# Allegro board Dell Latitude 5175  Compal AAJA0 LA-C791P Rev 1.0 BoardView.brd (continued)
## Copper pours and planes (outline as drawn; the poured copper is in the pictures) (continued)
CPU_B+ on TOP (solid shape): 108.91,124.06 108.91,117.72 108.81,117.62 108.81,114.33 108.9,114.24 108.9,113.72 108.97,113.66 109.58,113.66 109.6,113.63 109.6,112.97 109.55,112.92 106.86,112.92 106.32,113.45 106.32,116.56 106.9,116.56 106.9,117.45 106.32,117.45 106.32,117.77 106.9,117.77 106.9,118.6 106.32,118.6 106.32,119.09 106.78,119.55 106.78,120.82 106.79,120.84 106.79,122.13 106.79,122.14 106.79,123.87 107.09,124.17 108.81,124.17
CPU_B+ on BOTTOM (solid shape): 112.5,121.27 112.5,117.66 112.39,117.55 112.29,117.55 112.17,117.66 112.17,121.28 112.23,121.35 112.43,121.35
CPU_B+ on BOTTOM (solid shape): 109.97,125.83 109.97,115.95 109.65,115.64 109.65,114.98 109.58,114.9 108.25,114.9 108.17,114.99 108.17,115.5 108.64,115.97 108.64,125.73 108.78,125.87 109.93,125.87
CPU_B+ on BOTTOM (solid shape): outline of 94 points within 103.99,106.84 109.56,112.47
CPU_B+ on GND1 (solid shape): 109.04,124.54 109.04,123.33 108.94,123.23 106.97,123.23 106.85,123.35 106.85,124.69 107,124.84 108.73,124.84
CPU_B+ on GND3 (solid shape): 109.89,125.05 109.89,124.32 109.89,124.32 109.89,123.87 109.84,123.72 109.87,123.56 109.8,123.49 106.88,123.49 106.82,123.55 106.82,124.69 106.93,124.8 108.64,124.8 109.05,125.21 109.73,125.21
CPU_B+ on IN4: 105.97,109.47 105.78,109.66 105.78,115.84 106.58,116.63 106.58,125 106.86,125.28 109.54,125.28 110.02,124.79 110.02,123.76 112.43,121.35 112.43,117.45 111.36,116.38 111.36,115.7 110.13,114.48 110.13,109.86 109.74,109.47
D1_PVCC_GT on BOTTOM (solid shape): 113.3,122.7 113.3,121.84 112.98,121.52 112.98,121.12 112.93,121.07 112.67,121.07 112.61,121.14 112.61,121.31 112.6,121.32 112.6,122.62 112.71,122.73 113.27,122.73
D8_PVCC_IA on BOTTOM (solid shape): 113.03,117.85 113.03,116.25 112.95,116.17 112.46,116.17 112.34,116.28 112.34,117.24 112.67,117.57 112.67,117.82 112.75,117.9 112.98,117.9
DCPDSW_1P0 on BOTTOM (solid shape): 60.79,118.6 60.87,118.6 60.87,118.56 60.89,118.5 60.92,118.44 60.92,118.42 60.99,118.35 60.99,118.22 60.92,118.14 60.84,118.14 60.82,118.17 60.72,118.17 60.71,118.17 60.51,118.18 60.37,118.04 60.37,118.03 60.19,117.84 59.83,117.84 59.58,117.59 58.06,117.59 57.99,117.67 57.99,118.38 58.04,118.43 58.81,118.43 59.09,118.71 60.68,118.71
DDR_0_DQ_VREF on TOP (solid shape): 88.85,130.5 88.85,129.76 88.7,129.61 88.14,129.61 88,129.75 87.25,129.75 87.22,129.71 87.22,129.21 87.16,129.16 86.86,129.16 86.79,129.22 86.79,130.58 86.86,130.65 88.7,130.65
DDR_1_DQ_VREF on TOP (solid shape): 60.32,137.91 60.32,135.69 60.57,135.44 60.57,135.12 60.49,135.04 60.29,135.04 59.87,135.45 59.87,137.86 59.97,137.96 60.27,137.96
DDR_1_DQ_VREF on TOP (solid shape): 82.96,130.09 82.96,129.45 83.08,129.33 83.85,129.33 84.02,129.15 84.02,128.74 83.97,128.69 82.32,128.69 82.19,128.82 82.19,130.09 82.32,130.22 82.83,130.22
DDR_1_DQ_VREF on IN1 (solid shape): 82.91,130.06 82.91,129.81 82.75,129.66 78.16,129.66 78.08,129.73 78.08,130.01 78.23,130.16 82.8,130.16
DDR_VREF_CA on TOP (solid shape): 90.37,126.3 90.37,124.75 90.73,124.4 91.62,124.4 91.69,124.32 91.69,123.74 91.62,123.66 91.6,123.66 91.59,123.68 91.29,123.68 91.28,123.66 90.63,123.66 90.5,123.54 90.5,123.1 90.47,123.08 89.84,123.08 89.71,123.21 89.71,123.71 89.51,123.92 88.49,123.92 88.25,123.68 87.59,123.68 87.53,123.74 87.53,124.37 87.55,124.4 89.71,124.4 89.86,124.55 89.86,125.36 89.66,125.57 87.86,125.57 87.78,125.64 87.78,126.28 87.91,126.41 90.27,126.41
DDR_VREF_CA on BOTTOM (solid shape): 72.06,134.8 73.25,134.8 73.31,134.74 73.31,134.43 73.27,134.39 73.09,134.39 72.95,134.26 71.88,134.26 70.06,136.08 69.68,136.08 69.63,136.13 69.63,136.37 69.66,136.41 70.45,136.41
EN_0.95V_PRIM on TOP (solid shape): 178.76,104.26 178.76,102.78 178.64,102.66 177.55,102.66 177.09,103.11 175.77,103.11 175.72,103.16 175.72,103.32 175.77,103.37 177.06,103.37 178,104.31 178.71,104.31
EN_1.0V_PRIM on BOTTOM (solid shape): 174.75,117.46 174.75,116.96 174.68,116.88 173.96,116.88 173.68,117.16 172.49,117.16 172.44,117.21 172.44,117.95 172.54,118.05 174.17,118.05
EN_1.0V_PRIM on IN4 (solid shape): 171.61,118.33 171.81,118.23 172,118.33 172.01,118.35 172.54,118.35 172.55,118.33 172.63,118.26 172.73,118.23 172.75,118.23 173.08,117.9 173.08,117.31 173,117.24 172.63,117.24 172.4,117.46 172.4,117.66 172.26,117.8 171.66,117.8 171.53,117.66 171.33,117.66 171.27,117.72 171.27,118.25 171.37,118.35 171.6,118.35
H6_IMON_SA on TOP (solid shape): 117.7,116.5 118.5,116.5 118.57,116.43 118.57,115.91 118.47,115.81 116.98,115.81 116.81,115.98 116.81,116.65 116.69,116.78 116.69,117.04 116.78,117.13 117.07,117.13
ILMT_1.0V on IN3 (solid shape): 174.75,116.58 174.75,116.09 174.65,115.99 173.94,115.99 172.47,117.46 172.47,118.43 172.62,118.58 172.75,118.58
JUSBC1_GND on BOTTOM (solid shape): 20.83,27.35 21.54,27.35 21.77,27.12 21.77,25.52 21.64,25.39 18.69,25.39 18.59,25.49 18.59,25.95 18.44,26.1 15.75,26.1 15.33,25.68 15.16,25.68 14.1,24.63 12.72,24.63 12.6,24.75 12.6,25.75 12.79,25.94 14.19,25.94 16,27.75 20.42,27.75
JUSBC1_GND on BOTTOM (solid shape): 6.95,20.91 6.95,20.34 5.38,18.77 5.38,13.34 7.02,11.7 7.9,11.7 8.28,12.08 8.28,16.82 9.58,16.82 9.58,16.77 9.58,16.71 9.6,16.67 9.62,16.62 9.65,16.58 9.69,16.54 9.73,16.51 9.78,16.49 9.83,16.47 9.88,16.46 9.93,16.46 9.98,16.47 10.03,16.49 10.08,16.51 10.12,16.54 10.16,16.58 10.19,16.62 10.21,16.67 10.23,16.71 10.24,16.77 10.24,16.82 10.23,16.87 10.21,16.92 10.19,16.97 10.16,17.01 10.12,17.04 10.08,17.07 10.03,17.1 9.98,17.11 9.93,17.12 9.88,17.12 9.83,17.11 9.78,17.1 9.73,17.07 9.69,17.04 9.65,17.01 9.62,16.97 9.6,16.92 9.58,16.87 9.58,16.82 8.28,16.82 8.28,19.33 8.51,19.56 9.74,19.56 11.09,20.91 13.93,20.91 14.1,20.74 14.1,9.96 13.66,9.53 4.71,9.53 4.31,9.93 2.01,9.93 1.93,10.01 1.93,20.61 2.41,21.1 6.76,21.1
JUSBC1_GND on IN4 (solid shape): 13.64,25.59 13.64,23.85 12.59,22.8 12.59,21.77 13.36,21 13.36,20.59 13.26,20.49 10.95,20.49 10.79,20.64 10.79,22.21 11.35,22.77 11.35,25.19 11.96,25.8 13.44,25.8
LDO_3V on BOTTOM (solid shape): 174.61,115.36 174.63,115.36 174.66,115.35 174.72,115.32 174.73,115.26 174.73,115.23 174.73,115.18 174.73,115.08 174.7,115.05 174.02,115.05 173.18,114.21 172.49,114.21 172.39,114.32 172.39,115.2 172.52,115.33 174.17,115.33 174.19,115.34 174.22,115.35 174.25,115.36
LDO_IN on BOTTOM (solid shape): 201.68,109.95 201.68,109.29 201.9,109.06 202.65,109.06 202.82,109.23 202.82,109.71 202.92,109.81 203.42,109.81 203.48,109.74 203.48,108.88 202.8,108.19 202.01,108.19 201.84,108.02 201.84,107.24 201.65,107.05 195.63,107.05 195.22,107.46 195.22,108.52 195.5,108.8 198.86,108.8 199.12,109.07 199.12,109.98 199.3,110.16 201.46,110.16
LP_0.95V on TOP (solid shape): 178.89,106.87 178.89,105.48 178.77,105.36 178.77,104.66 178.67,104.56 177.88,104.56 176.91,103.6 175.77,103.6 175.72,103.65 175.72,103.75 175.82,103.85 176.71,103.85 176.91,104.05 176.91,105.86 178.1,107.05 178.71,107.05
LX_0.85VS_VCCIO on TOP (solid shape): 39.93,137.02 39.93,136.16 40.51,135.58 40.51,134.03 40.49,134 38,134 37.95,134.05 37.95,135.65 38.23,135.93 38.86,135.93 39.12,136.18 39.12,137.05 39.19,137.12 39.83,137.12
LX_0.95V on TOP (solid shape): 179.83,108.5 179.83,107.36 179.7,107.23 177.83,107.23 177.09,106.49 175.36,106.49 174.98,106.11 174.98,105.2 174.83,105.04 174.29,105.04 174.19,105.15 174.19,106.06 173.63,106.62 173.63,108.42 173.91,108.7 179.63,108.7
LX_1.0V on BOTTOM (solid shape): 178.1,118 177.9,117.8 176.89,117.8 176.78,117.68 176.78,116.36 175.33,116.36 175.33,117.7 175.23,117.8 174.78,117.8 173.91,118.66 173.91,120.74 174.12,120.94 178.1,120.94
LX_1.8V on TOP (solid shape): 38.53,114.29 38.53,110.53 38.23,110.23 35.38,110.23 35.25,110.35 35.25,110.96 35.41,111.11 36.35,111.11 36.45,111.22 36.45,111.33 37.3,111.33 37.3,111.28 37.31,111.23 37.32,111.18 37.35,111.13 37.38,111.09 37.41,111.05 37.46,111.02 37.5,111 37.55,110.98 37.6,110.97 37.66,110.97 37.71,110.98 37.76,111 37.8,111.02 37.85,111.05 37.88,111.09 37.91,111.13 37.94,111.18 37.95,111.23 37.96,111.28 37.96,111.33 37.95,111.38 37.94,111.43 37.91,111.48 37.88,111.52 37.85,111.56 37.8,111.59 37.76,111.61 37.71,111.63 37.66,111.64 37.6,111.64 37.55,111.63 37.5,111.61 37.46,111.59 37.41,111.56 37.38,111.52 37.35,111.48 37.32,111.43 37.31,111.38 37.3,111.33 36.45,111.33 36.45,111.75 36.27,111.93 35.31,111.93 35.2,112.03 35.2,112.18 35.25,112.23 36.55,112.23 36.8,112.49 36.8,114.42 36.88,114.5 38.33,114.5
PLL_COMP1 on TOP (solid shape): 133.12,126.94 133.12,126.53 132.84,126.25 132.84,125.9 132.71,125.77 130.23,125.77 129.64,126.35 129.64,126.61 129.74,126.71 129.84,126.71 129.9,126.66 129.9,126.43 130.07,126.25 130.1,126.25 130.25,126.1 132.05,126.1 132.09,126.14 132.13,126.14 132.96,126.96 133.1,126.96
PLL_COMP2 on TOP (solid shape): 129.49,126.61 129.49,126.28 130.2,125.57 132.18,125.57 132.31,125.44 132.82,125.44 132.92,125.34 132.92,124.15 132.87,124.09 132.31,124.09 131.95,124.45 131.95,125.03 131.8,125.19 130.2,125.19 129.21,126.18 129.21,126.53 129.21,126.61 129.29,126.69 129.41,126.69
PLL_VDD on TOP (solid shape): 129.06,126.69 129.06,126.18 130.17,125.06 130.81,125.06 130.86,125.01 130.86,124.6 130.66,124.4 130.17,124.4 129.79,124.78 129.79,125.06 128.85,126 128.85,126.69 128.88,126.71 129.04,126.71
RING2 on TOP (solid shape): 5.65,145.92 5.65,145.62 5.6,145.57 5.6,144.95 5.61,144.95 5.99,144.95 6.28,145.23 7.11,145.23 7.51,144.83 7.51,143.72 7.94,143.29 8.34,143.29 8.5,143.14 8.5,142.69 8.6,142.58 8.6,142.25 8.33,141.98 8.33,141.34 8.67,141 9.46,141 9.55,140.91 9.55,140.21 9.48,140.14 8.98,140.14 8.81,139.97 8.81,139.56 9.12,139.25 9.12,138.95 9.05,138.89 8.22,138.89 8,139.1 8,141.24 7.82,141.42 7.82,142.28 8.19,142.65 8.19,142.67 8,142.87 7.54,142.87 6.82,143.59 6.82,144.44 6.68,144.58 5.77,144.58 5.77,144.59 4.98,144.59 4.95,144.61 4.95,145.04 4.71,145.29 4.41,145.29 4.14,145.55 4.14,146.27 4.3,146.43 5.14,146.43
RING2_L on IN1 (solid shape): 8.6,131.56 8.6,130.61 8.31,130.31 7.65,130.31 7.5,130.46 7.5,130.5 7.17,130.84 7.17,131.36 7.7,131.89 8.27,131.89
RING2_L on IN1 (solid shape): 11.06,140.98 11.06,139.09 10.95,138.98 10.67,138.98 10.64,139 10.17,139 10.08,139.09 10.08,140.07 9.78,140.38 9.78,140.99 10.01,141.21 10.82,141.21
RING2_L on IN3 (solid shape): 7.95,130.55 8.74,130.55 8.79,130.49 8.79,130.35 8.74,130.29 8.05,130.29 7.89,130.14 7.41,130.14 7.12,130.43 7.12,130.92 7.23,131.03 7.47,131.03
RING2_L on GND3 (solid shape): 8.03,130.55 8.7,130.55 8.77,130.48 8.77,130.37 8.69,130.29 8.55,130.29 7.57,130.29 7.13,130.73 7.13,130.96 7.29,131.12 7.46,131.12
RING2_L on TOP: 9.75,141.32 10.26,141.32 10.39,141.19 10.39,140.01 9.91,139.54 9.57,139.54 9.51,139.6 9.51,139.95 9.68,140.12 9.68,141.24
SIM_VCC on TOP (solid shape): 213.74,101.64 213.74,100.12 213.69,100.07 213.08,100.07 212.98,100.17 212.98,101.56 213.13,101.72 213.66,101.72
SLEEVE on TOP (solid shape): 9.96,145.2 9.96,144.53 10.08,144.41 10.08,143.69 10.08,143.61 9.69,143.22 9.61,143.22 9.49,143.1 9.49,142.95 10.08,142.37 10.93,142.37 10.99,142.31 10.99,142.04 10.94,141.98 9.7,141.98 9.22,142.46 8.97,142.88 8.97,143.12 8.98,143.12 9.4,143.55 9.61,143.55 9.72,143.66 9.72,144.4 9.57,144.55 9.57,144.97 9.53,145.01 8.75,145.01 8.53,144.8 8.53,144.63 8.49,144.59 7.74,144.59 7.7,144.63 7.7,145.21 7.74,145.25 9.91,145.25
SLEEVE on IN4: 11.5,142.58 12.39,142.58 15.74,145.93 15.74,153.94 13.05,156.63 3.41,156.63 2.94,156.16 2.94,155.04 3.07,154.91 5.14,154.91 5.3,155.06 5.3,155.91 5.45,156.07 12.97,156.07 14.16,154.88 14.16,154.87 15.06,153.97 15.06,146.56 12.4,143.9 11.14,143.9 10.34,143.1 10.34,142.65 10.41,142.58 11.5,142.58
SLEEVE_L on IN1 (solid shape): 8.63,144.22 8.63,143.83 8.35,143.55 7.58,143.55 7.51,143.61 7.51,144.4 7.65,144.54 8.31,144.54
SLEEVE_L on IN3 (solid shape): 8.53,132.15 8.53,131.56 8.76,131.33 8.76,130.75 8.71,130.7 8.05,130.7 7.54,131.21 7.54,132.15 7.65,132.25 8.43,132.25
SLEEVE_L on IN3 (solid shape): 8.56,144.08 8.56,142.59 8.48,142.51 7.92,142.51 7.54,142.89 7.54,144.26 7.8,144.52 8.12,144.52
SPK_L+ on BOTTOM (solid shape): 21.72,85.49 21.72,84.2 21.06,83.54 21.06,80.56 20.75,80.25 20.01,80.25 19.81,80.46 19.81,82.74 20.19,83.12 20.19,84.14 20.32,84.27 20.32,85.38 20.5,85.56 21.64,85.56
SPK_L+_L on TOP (solid shape): 43.94,80.03 43.94,79.31 43.89,79.26 43.51,79.26 43.41,79.16 43.41,78.81 43.31,78.7 42.72,78.7 42.67,78.76 42.67,79.64 43.09,80.06 43.9,80.06
SPK_L+_L on BOTTOM (solid shape): 22.47,87.32 22.47,85.79 22.42,85.74 20.88,85.74 20.83,85.79 20.83,86.58 20.88,86.63 21.5,86.63 21.58,86.7 21.58,87.29 21.67,87.39 22.4,87.39
SPK_L+_L on GND1 (solid shape): 43.94,80 43.94,79.34 43.81,79.21 42.87,79.21 42.77,79.31 42.77,79.57 43.31,80.1 43.84,80.1
SPK_L+_L on IN1 (solid shape): 43.94,80 43.94,79.34 43.81,79.21 42.87,79.21 42.77,79.31 42.77,79.57 43.31,80.1 43.84,80.1
SPK_L+_L on IN3 (solid shape): 23.41,86.79 23.41,86.03 23.23,85.85 22.85,85.85 21.78,86.93 21.78,87.3 21.86,87.38 22.82,87.38
SPK_L+_L on IN3 (solid shape): 43.6,79.79 43.6,79.25 43.33,78.98 41.91,78.98 41.91,78.98 41.71,78.98 41.62,79.08 41.62,79.92 41.7,80.01 43.39,80.01
SPK_L- on BOTTOM (solid shape): 19.51,85.54 19.51,85.03 19.46,84.98 19.08,84.98 18.97,84.88 18.97,83.15 19.56,82.57 19.56,80.36 19.41,80.2 18.8,80.2 17.93,81.07 17.93,85.36 18.14,85.56 19.48,85.56
SPK_L-_R on TOP (solid shape): 43.94,78.53 43.94,77.82 43.89,77.76 43.46,77.76 43.36,77.66 43.36,77.54 43.33,77.51 42.67,77.51 42.67,78.5 42.75,78.58 43.89,78.58
SPK_L-_R on IN3 (solid shape): 43.61,78.3 43.61,77.97 43.31,77.67 41.92,77.67 41.82,77.77 41.82,78.59 41.93,78.7 43.21,78.7
SPK_L-_R on IN3 (solid shape): 21.42,88.22 21.42,86.45 21.37,86.4 20.51,86.4 20.38,86.53 20.38,87.9 20.39,87.9 20.39,88.23 20.49,88.33 21.31,88.33
SPK_R+_L on TOP (solid shape): 44.17,84.14 44.17,83.61 44.02,83.45 43.61,83.45 43.51,83.35 43.51,83.1 43.33,82.92 42.72,82.92 42.7,82.95 42.7,83.94 42.77,84.01 43.28,84.01 43.54,84.27 44.04,84.27
SPK_R+_L on GND1 (solid shape): 44.09,84.24 44.09,83.75 43.94,83.6 43.6,83.6 42.8,84.39 42.8,84.62 42.91,84.73 43.61,84.73
SPK_R+_L on IN1 (solid shape): 43.2,84.64 43.7,84.64 44.11,84.23 44.11,83.76 43.94,83.6 43.6,83.6 42.8,84.39 42.8,84.62 42.88,84.7 43.14,84.7
SPK_R+_L on IN2 (solid shape): 44.09,84.24 44.09,83.75 43.94,83.6 43.24,83.6 42.67,84.17 42.67,84.89 43.45,84.89
SPK_R+_L on IN2 (solid shape): 207.09,95.35 207.09,95.17 207.09,95.16 207.09,94.56 206.92,94.39 205.4,94.39 205.24,94.55 205.24,95.41 205.31,95.49 206.95,95.49
SPK_R+_L on IN3 (solid shape): 207.19,95.38 207.19,94.52 207.06,94.39 206.22,94.39 206.09,94.52 206.09,95.29 206.1,95.29 206.1,95.44 206.15,95.49 207.07,95.49
SPK_R+_L on GND3 (solid shape): 207.19,95.24 207.19,94.52 207.06,94.39 206.22,94.39 206.09,94.52 206.09,95.26 206.31,95.48 206.95,95.48
SPK_R+_L on IN4 (solid shape): 207.12,94.48 207.03,94.39 206.19,94.39 206.12,94.47 206.12,96.12 206.3,96.3 207.12,96.3
SPK_R+_L on IN4 (solid shape): 217.56,103.71 217.56,103.57 216.52,102.53 215.98,102.53 215.83,102.69 215.83,103.25 216.36,103.79 217.48,103.79
SPK_R+_L on BOTTOM: 216.33,108.59 216.33,105.35 216.33,105.34 216.33,103.72 216.53,103.51 217.47,103.51 217.87,103.92 217.87,108.32 217.93,108.38 218.15,108.38 218.15,108.4 218.17,108.43 218.17,109.73 218.1,109.8 217.54,109.8
SPK_R-_R on TOP (solid shape): 44.02,86.1 44.02,84.93 43.34,84.25 42.7,84.25 42.7,85.13 42.8,85.23 42.9,85.23 43.08,85.41 43.08,86.15 43.15,86.22 43.89,86.22
SPK_R-_R on IN1 (solid shape): 44.22,87.19 44.22,85.42 44.14,85.34 43.43,85.34 42.33,86.45 42.33,88.24 42.47,88.38 43.03,88.38
SPK_R-_R on IN1 (solid shape): 204.79,94.46 205.4,94.46 205.72,94.15 205.72,93.54 205.57,93.39 204.1,93.39 203.54,93.95 203.54,94.65 203.66,94.77 204.48,94.77
SPK_R-_R on IN3 (solid shape): 205.79,94.76 205.79,93.49 205.7,93.39 204.87,93.39 204.73,93.53 204.73,94.81 204.79,94.87 205.69,94.87
SPK_R-_R on GND3 (solid shape): 205.84,94.77 205.84,93.55 205.65,93.36 204.87,93.36 204.66,93.57 204.66,94.72 204.8,94.87 205.74,94.87
SPK_R-_R on IN4 (solid shape): 205.84,95.54 205.84,94.38 205.74,94.27 204.91,94.27 204.83,94.36 204.83,95.38 204.82,95.39 204.82,95.61 205.77,95.61
SPK_R-_R on IN4 (solid shape): 221.96,109.21 221.96,107.63 221.36,107.02 220.74,107.02 220.61,107.15 220.61,109.09 220.89,109.38 221.79,109.38
SPK_R-_R on BOTTOM: 220.61,108.34 221.88,108.34 221.99,108.46 221.99,109.59 221.89,109.7 221.26,109.7 221.18,109.78 220.6,109.78 220.54,109.72 220.54,108.41
SW on BOTTOM (solid shape): 123.53,111.03 123.53,110.47 123.77,110.23 124.54,110.23 124.69,110.07 126.03,110.07 126.09,110.02 126.09,109.87 126.01,109.79 125.27,109.79 124.96,109.48 124.96,109.32 124.41,108.78 121.61,108.78 121.51,108.88 121.51,110.81 121.83,111.13 123.43,111.13
N1728290 on TOP (solid shape): 106.67,112.76 109.57,112.76 109.63,112.7 109.63,111.78 109.56,111.71 106.99,111.71 106.78,111.5 106.78,110.2 106.89,110.09 107.55,110.09 107.58,110.06 107.58,109.54 107.51,109.47 106.99,109.47 106.87,109.35 106.87,107.98 106.72,107.83 104.3,107.83 104,108.14 104,108.84 103.82,109.02 102.5,109.02 102.4,109.12 102.4,110.95 102.57,111.12 103.64,111.12 103.81,111.28 103.81,112.97 103.98,113.14 106.29,113.14
N1728978 on TOP (solid shape): 108.74,108.58 108.74,107.87 108.8,107.82 109.69,107.82 109.75,107.75 109.75,107.24 109.67,107.15 108.86,107.15 108.08,107.93 108.08,108.63 108.11,108.67 108.65,108.67
N1728978 on IN1 (solid shape): 109.7,110.97 109.7,109.06 108.6,107.97 108.38,107.97 108.29,108.06 108.29,108.57 109.18,109.46 109.18,110.88 109.35,111.05 109.62,111.05
N16334024 on TOP (solid shape): 146.89,114.09 148.13,114.09 148.34,113.88 148.34,109.84 148.16,109.67 146.59,109.67 146.44,109.82 146.44,112.91 146.29,113.05 144.18,113.05 144.12,113.12 144.12,114.25 144.24,114.37 146.61,114.37
N16334844 on BOTTOM (solid shape): 134.49,120.69 134.49,119.27 135.18,118.58 135.18,116.5 135.05,116.37 134.49,116.37 134.49,117.77 134.16,118.1 133.83,117.77 133.83,116.37 132.84,116.37 132.51,116.7 132.51,120.54 132.8,120.83 134.35,120.83
N16335894 on TOP (solid shape): 141.53,113.02 141.53,112.21 141.45,112.13 140.3,112.13 139.87,111.7 138.3,111.7 138.18,111.83 138.18,112.89 138.4,113.12 141.43,113.12
N16336052 on TOP (solid shape): 144.95,112.72 144.95,111.93 145.02,111.86 145.81,111.86 145.84,111.82 145.84,111.33 145.82,111.3 144.42,111.3 144.37,111.35 144.37,112.74 144.41,112.78 144.9,112.78
N16336052 on IN3 (solid shape): 144.27,112.77 144.42,112.71 144.58,112.77 145.06,112.77 145.29,112.54 145.29,111.93 145.21,111.85 144.91,111.85 144.53,112.23 144.49,112.23 144.32,112.33 144.14,112.32 144.04,112.41 144.04,112.72 144.09,112.77
N16337211 on BOTTOM (solid shape): 162.67,119.48 162.67,117.91 162.67,116.92 162.79,116.8 163.65,116.8 163.86,116.6 163.86,115.66 163.73,115.53 162.64,115.53 162.28,115.18 162.28,113.91 162.05,113.68 161.14,113.68 161.01,113.55 161.01,112.99 160.86,112.84 160.07,112.84 159.87,112.64 158.88,112.64 158.72,112.79 158.72,114.57 159.99,115.84 159.99,116.25 161.43,116.25 161.79,116.6 161.43,116.96 159.99,116.96 159.99,117.54 160.12,117.67 160.65,117.67 160.96,117.97 160.96,119.4 161.16,119.6 162.56,119.6
N16337658 on BOTTOM (solid shape): 161.92,112.54 161.92,111.67 160.73,110.48 160.66,110.48 160.65,110.49 160.58,110.52 160.5,110.53 160.35,110.53 160.04,110.22 160.35,109.91 160.73,109.91 160.73,107.99 160.58,107.84 159.74,107.84 159.41,108.17 159.41,108.52 159.18,108.75 158.67,108.75 158.53,108.89 158.53,110.8 159.36,111.62 160.83,111.62 161.11,111.9 161.11,112.49 161.24,112.61 161.85,112.61
N16337658 on IN4 (solid shape): 163.83,112.54 163.83,111.83 161.14,111.83 161.09,111.88 161.09,112.46 161.24,112.61 163.75,112.61
N16337829 on BOTTOM (solid shape): 159.26,108.47 159.26,108.02 159.92,107.36 159.92,106.49 159.84,106.42 159.28,106.42 159.23,106.47 159.23,107.05 158.67,107.61 158.67,108.5 158.75,108.57 159.16,108.57
N16338670 on IN3 (solid shape): 161.82,113.4 161.82,111.6 160.73,110.51 160.73,110.12 160.58,109.97 160.2,109.97 160.07,110.1 160.07,110.91 161.19,112.03 161.19,113.3 161.34,113.45 161.77,113.45
N16338676 on BOTTOM (solid shape): 164.54,114.39 164.54,112.89 164.46,112.82 162.13,112.82 162.08,112.87 162.08,113.43 162.2,113.55 163.78,113.55 163.94,113.72 163.94,114.25 164.11,114.42 164.52,114.42
N16355483 on BOTTOM (solid shape): 151.66,110.58 151.66,110.02 151.79,109.9 151.91,109.9 151.91,109.89 152.23,109.89 152.25,109.9 152.37,109.77 152.37,108.07 152.15,107.84 151.41,107.84 151.16,108.09 151.16,108.65 151,108.8 150.47,108.8 150.34,108.93 150.34,110.66 150.47,110.78 151.46,110.78
N16355483 on IN4 (solid shape): 153.59,112.13 153.59,111.75 152.37,110.53 152.37,109.41 152.32,109.36 151.84,109.36 151.71,109.49 151.71,110.73 153.19,112.21 153.52,112.21
N16355838 on IN4 (solid shape): 152.65,112.03 152.65,111.85 151.59,110.79 151.59,110.78 151.26,110.45 151.26,108.47 151.09,108.31 150.61,108.31 150.55,108.37 150.55,110.89 151.87,112.21 152.48,112.21
N16356132 on BOTTOM (solid shape): 150.19,107.33 150.19,106.16 150.14,106.11 149.61,106.11 149.4,105.91 149.4,105.15 149.3,105.04 148.69,105.04 148.56,105.17 148.56,107.46 148.69,107.58 149.94,107.58
N17240153 on TOP (solid shape): 37.77,106.64 37.77,105.93 37.52,105.68 37.26,105.68 36.88,105.3 36.88,104.69 36.81,104.62 36.67,104.62 36.6,104.69 36.6,105.4 36.58,105.43 36.47,105.43 36.45,105.4 36.45,104.69 36.4,104.64 36.25,104.64 36.19,104.69 36.19,105.75 36.63,106.19 36.63,106.55 36.74,106.66 37.75,106.66
N17242608 on TOP (solid shape): 107.21,127.27 107.21,126.61 107.06,126.46 106.45,126.46 106.3,126.3 105.38,126.3 105.31,126.38 105.31,127.22 105.38,127.29 107.19,127.29
N17243834 on TOP (solid shape): 209.46,127.82 209.46,126.72 209.42,126.69 208.74,126.69 208.53,126.48 207.49,126.48 207.44,126.54 207.44,127.85 207.49,127.9 209.37,127.9
N17302218 on TOP (solid shape): 48.26,102.68 48.26,102.15 47.57,101.46 47.57,100.65 47.41,100.5 46.91,100.5 46.79,100.62 46.79,102.35 47.17,102.73 48.21,102.73
N17303773 on TOP (solid shape): 208.97,124.91 209.34,124.91 209.4,124.84 209.4,123.58 209.11,123.28 207.63,123.28 207.44,123.47 207.44,125.11 207.49,125.16 208.71,125.16
N17587387 on TOP (solid shape): 41.17,78.43 41.96,78.43 41.96,77.51 41.94,77.49 41.15,77.49 40.46,78.17 40.46,78.93 40.67,78.93
N17587389 on TOP (solid shape): 40.33,79.77 41.88,79.77 41.96,79.7 41.96,78.73 41.94,78.7 41.07,78.7 39.78,80 38.86,80 38.79,80.08 38.79,80.15 38.84,80.2 39.9,80.2
N17587465 on TOP (solid shape): 41.92,83.86 41.92,83.07 41.12,83.07 40.79,82.74 40.68,82.86 40.68,83.76 40.8,83.89 41.9,83.89
N17587467 on TOP (solid shape): 41.96,84.24 40.89,84.24 40.51,83.86 40.51,83 39.9,82.39 38.86,82.39 38.81,82.44 38.81,82.54 38.86,82.59 39.78,82.59 40.16,82.97 40.16,84.39 40.92,85.16 41.96,85.16
N19043300 on TOP (solid shape): 106.36,107.04 106.36,106.61 106.51,106.47 106.82,106.47 106.85,106.43 106.85,105.68 106.81,105.63 105.62,105.63 105.53,105.72 105.53,107.04 105.65,107.16 106.24,107.16
N19043300 on TOP (solid shape): 110.18,114.25 110.18,112.91 110.11,112.84 109.8,112.84 109.73,112.92 109.73,113.68 109.62,113.79 109.14,113.79 109.08,113.85 109.08,114.24 109.18,114.34 110.09,114.34
N19043300 on IN1 (solid shape): 110.03,113.48 110.03,112.94 109.98,112.89 107.6,112.89 106.38,111.67 106.38,107 106.14,106.76 105.62,106.76 105.53,106.85 105.53,112.28 106.82,113.58 109.93,113.58
N19043343 on IN1 (solid shape): 109.88,108.49 109.88,108.09 107.7,105.9 107.11,105.9 107.07,105.94 107.07,106.4 107.16,106.49 107.33,106.49 109.42,108.58 109.8,108.58
N19643413 on BOTTOM (solid shape): 177.2,103.9 177.2,103.16 177.1,103.06 176.16,103.06 176.09,102.99 175.21,102.99 175.13,103.07 175.13,103.98 175.25,104.1 177,104.1
N19643415 on BOTTOM (solid shape): 177.2,102.85 177.2,102.59 177.13,102.52 176.42,102.52 175.91,102.01 175.22,102.01 175.15,102.09 175.15,102.75 175.25,102.85 176.14,102.85 176.21,102.92 177.13,102.92
N20422143 on BOTTOM (solid shape): 120.22,113.38 120.22,111.24 120.42,111.04 120.42,108.83 120.37,108.78 119.18,108.78 118.71,109.25 118.71,109.76 118.31,110.15 117.42,110.15 117.17,110.4 117.17,112.89 117.84,113.57 120.03,113.57
N21234656 on TOP (solid shape): 48.23,105.04 48.23,104.18 48.16,104.1 46.96,104.1 46.76,104.31 46.2,104.31 46.19,104.32 46.19,105.28 46.23,105.32 47.95,105.32
N21235869 on BOTTOM (solid shape): 63.98,100.94 63.98,100.94 63.98,100.35 64.49,99.84 64.49,99.1 64.41,99.02 64.34,99.02 64.29,99.08 64.29,99.74 64.26,99.76 64.13,99.76 64.11,99.74 64.11,99.08 64.06,99.02 63.4,99.02 63.3,99.13 63.3,99.63 63.31,99.66 63.42,99.67 63.55,99.81 63.55,100 63.42,100.13 63.26,100.13 63.04,100.35 63.04,100.99 63.06,101.01 63.91,101.01
N21485395 on BOTTOM (solid shape): 200.13,113.71 201.57,113.71 201.72,113.55 201.72,112.1 201.22,111.6 199.36,111.6 199.03,111.93 199.03,113.86 199.07,113.9 199.93,113.9
N21534226 on TOP (solid shape): 144.34,121.73 144.34,119.85 144.28,119.8 142.71,119.8 142.65,119.87 142.65,120.96 142.87,121.19 142.87,122.23 142.9,122.25 143.81,122.25
N21616168 on BOTTOM (solid shape): 173.48,115.89 174.17,115.89 174.21,115.88 174.25,115.88 174.61,115.88 174.65,115.88 174.69,115.89 174.7,115.89 174.8,115.79 174.8,115.56 174.71,115.46 174.66,115.48 174.61,115.49 174.25,115.49 174.19,115.48 174.14,115.46 170.74,115.46 170.69,115.41 169.98,115.41 169.85,115.53 169.85,116.03 169.94,116.12 173.25,116.12
N21618504 on BOTTOM (solid shape): 192.1,118.58 192.1,117.54 192.4,117.24 193.98,117.24 194.11,117.11 194.11,115.97 193.95,115.81 193.65,115.81 193.45,115.61 193.45,114.87 193.31,114.74 189.81,114.74 189.43,114.37 189.43,112.23 189.38,112.18 189.15,112.18 189.07,112.27 189.07,112.55 188.8,112.82 188.47,112.82 188.34,112.94 188.34,113.43 188.23,113.54 186.18,113.54 185.47,114.25 185.47,118.63 185.7,118.86 191.82,118.86
N21622450 on BOTTOM (solid shape): 192.92,114.44 192.92,113.55 192.86,113.49 192.21,113.49 192.06,113.65 190.27,113.65 190.03,113.4 190.03,113.12 189.87,112.96 189.73,112.96 189.64,113.05 189.64,114.08 190.06,114.5 192.86,114.5
N21624147 on BOTTOM (solid shape): 33.02,120.23 33.02,116.63 32.94,116.55 30.35,116.55 30.1,116.8 30.1,117.72 29.77,118.05 27.51,118.05 27.43,118.13 27.43,118.28 27.53,118.38 27.94,118.38 29.21,119.65 29.21,119.95 29.51,120.26 32.99,120.26
N21628470 on TOP (solid shape): 123.62,125.92 123.62,125.29 123.77,125.14 124.54,125.14 124.61,125.06 124.61,124.32 124.54,124.25 123.22,124.25 123.09,124.37 123.09,125.97 123.16,126.05 123.49,126.05
N21628480 on BOTTOM (solid shape): 126.23,125.76 126.23,122.6 125.66,122.03 125.66,118.89 125.53,118.76 125.43,118.76 125.29,118.9 125.29,119.5 125.08,119.71 124.82,119.71 124.59,119.94 124.59,120.58 124.37,120.8 123.62,120.8 123.2,121.22 123.2,125.87 123.34,126.02 123.66,126.02 123.67,126.02 125.96,126.02
N21628589 on BOTTOM (solid shape): 126.4,119.32 126.4,117.69 126.72,117.36 126.72,115.86 126.44,115.59 125.93,115.59 125.76,115.41 125.76,114.77 125.68,114.7 125.04,114.7 124.96,114.79 124.96,115.27 124.9,115.32 124.07,115.32 123.98,115.23 123.01,115.23 122.78,115.46 122.78,116.35 123.29,116.86 125.5,116.86 125.81,117.16 125.81,119.34 125.97,119.5 126.22,119.5
N21630461 on BOTTOM (solid shape): 124.36,117.95 124.36,117.79 124.29,117.72 123.91,117.72 123.02,116.83 122.33,116.83 122.33,117.42 122.45,117.55 122.96,117.55 123.42,118 124.31,118
N21636274 on TOP (solid shape): 32.84,112.26 33.76,112.26 33.83,112.18 33.83,111.98 33.76,111.9 32.99,111.9 32.71,111.62 32.71,110.28 32.56,110.12 31.39,110.12 31.32,110.2 31.32,112.31 31.57,112.56 32.54,112.56
N21685380 on TOP (solid shape): 27.33,66.46 27.33,65.64 27.52,65.45 27.52,64.56 27.46,64.49 26.76,64.49 26.63,64.62 26.63,66.48 26.68,66.53 27.27,66.53
N21803574 on BOTTOM (solid shape): 180.14,106.59 180.14,105.64 179.67,105.17 179.67,105.03 178.92,104.28 177.29,104.28 177.23,104.34 177.23,105.47 177.33,105.57 179.24,105.57 179.5,105.82 179.5,106.59 179.56,106.66 180.07,106.66
N21803688 on BOTTOM (solid shape): 115.6,109.61 115.6,107.89 115.72,107.76 115.72,106.54 115.2,106.02 115.2,105.08 115.16,105.04 114.18,105.04 113.44,105.78 113.44,106.39 113.5,106.45 114.13,106.45 114.29,106.61 114.29,107.52 114.58,107.81 114.58,109.64 114.63,109.69 115.52,109.69
N22181898 on TOP (solid shape): 152.45,104.49 152.45,102.62 152.29,102.46 151.25,102.46 151.21,102.5 151.21,104.38 151.43,104.61 152.32,104.61
N22451929 on TOP (solid shape): 128.27,127.02 128.27,126.94 128.22,126.89 127.63,126.89 127.63,126.05 127.17,125.59 126.33,125.59 126.29,125.63 126.29,126.27 126.32,126.3 127,126.3 127.28,126.58 127.28,126.89 127.51,127.12 128.17,127.12
N22451931 on TOP (solid shape): 130.11,131.26 130.15,131.21 130.15,130.55 130.15,130.55 130.15,130.46 129.49,129.8 129.49,129.35 129.44,129.3 129.36,129.3 129.22,129.44 129.22,129.6 129.16,129.67 129.16,130.57 129.51,130.93 129.51,131.23 129.54,131.26
N22451933 on TOP (solid shape): 127.74,127.9 128.19,127.9 128.27,127.83 128.27,127.7 128.22,127.65 127.2,127.65 126.75,127.19 126.16,127.19 126.11,127.24 126.11,128.16 127.48,128.16
N22452420 on TOP (solid shape): 128.27,127.42 128.27,127.29 128.22,127.24 128.14,127.24 128.12,127.27 127.76,127.27 127.75,127.26 127.43,127.26 127.2,127.03 127.2,127.02 127.1,126.91 127.1,126.63 126.95,126.48 126.06,126.48 125.96,126.38 125.96,125.64 125.09,125.64 125.09,126.58 125.58,127.07 126.87,127.07 127.28,127.47 128.22,127.47
N22452424 on TOP (solid shape): 128.68,126.67 128.68,125.92 129.54,125.06 129.54,124.35 128.68,124.35 128.68,125.54 128.52,125.69 128.52,125.72 128.5,125.72 128.47,125.75 128.47,125.92 128.47,126.46 128.42,126.51 128.42,126.61 128.52,126.71 128.64,126.71
N22483924 on TOP (solid shape): 144.6,130.14 144.6,127.78 144.4,127.57 144.02,127.57 143.92,127.68 143.92,129.28 143.64,129.56 143.64,130.14 143.71,130.22 144.53,130.22
N22734897 on TOP (solid shape): 109.22,127.24 109.22,126.37 108.7,125.85 108.7,124.95 108.64,124.88 108,124.88 107.92,124.96 107.92,125.77 108.58,126.43 108.58,127.24 108.64,127.29 109.17,127.29
N22924832 on TOP (solid shape): 48.15,138.79 48.15,138.66 48.16,138.65 48.16,137.96 48.11,137.91 46.33,137.91 46.27,137.98 46.27,138.97 46.43,139.13 47.8,139.13
N23244273 on IN3: 66.05,106.81 66.05,107.32 66.31,107.57 66.56,107.57 66.61,107.52 66.61,107.04 66.46,106.89 66.46,106.33 66.38,106.25 66.07,106.25 65.98,106.16 65.81,106.16 65.71,106.26 65.71,106.47
N24228571 on BOTTOM (solid shape): 66.6,100.93 66.6,99.05 66.57,99.02 66.34,99.02 66.29,99.08 66.29,99.76 66.24,99.81 66.17,99.81 66.12,99.76 66.12,99.08 66.07,99.02 65.94,99.02 65.89,99.08 65.89,100.93 65.94,100.98 66.55,100.98
N24433868 on TOP (solid shape): 218.31,102.64 218.31,99.63 218.05,99.37 215.02,99.37 213.94,100.45 213.94,101.69 213.69,101.94 211.81,101.94 211.64,101.77 211.64,101.11 211.53,101 210.72,101 210.59,101.13 210.59,102.45 210.97,102.83 213.99,102.83 214.78,102.05 214.78,101 215.35,100.42 217.12,100.42 217.2,100.5 217.2,102.2 216.66,102.73 216.66,103.52 216.72,103.58 217.37,103.58
N24433875 on IN1 (solid shape): 214.6,100.15 214.6,99.71 214.07,99.18 213.18,99.18 212.86,99.49 212.86,99.87 213.04,100.04 213.81,100.04 214.04,100.26 214.49,100.26
N24544896 on BOTTOM (solid shape): 33.81,128.29 33.81,124.54 33.35,124.08 31.64,124.08 31.31,124.41 31.31,125.74 30.29,126.76 28.41,126.76 28.34,126.82 28.34,126.96 28.4,127.02 28.93,127.02 30.33,128.41 33.68,128.41
N24700151 on TOP (solid shape): 110.01,110.08 110.01,109.52 109.96,109.48 108,109.48 107.93,109.54 107.93,110.1 107.95,110.11 109.97,110.11
N25865128 on TOP (solid shape): 184.48,105.83 184.48,105.02 184.3,104.84 182.24,104.84 182.12,104.97 182.12,105.96 182.17,106.01 184.3,106.01
N25920196 on TOP (solid shape): 103.26,114.26 103.26,111.75 103.17,111.66 102.25,111.66 102.13,111.78 102.13,114.25 102.2,114.33 103.19,114.33
N51581707 on TOP: 37.49,72.11 36.93,71.55 36.93,70.61 37.1,70.44 38.79,70.44 39.38,71.03 39.38,72.03 39.3,72.11
N51584481 on TOP (solid shape): 34.85,106.62 34.85,104.69 34.8,104.64 34.65,104.64 34.59,104.69 34.59,105.37 34.57,105.4 34.49,105.4 34.44,105.35 34.44,104.71 34.39,104.66 34.21,104.66 34.16,104.71 34.16,105.22 34.03,105.35 33.47,105.35 33.37,105.45 33.37,106.54 33.48,106.66 34.81,106.66
N51592314 on TOP (solid shape): 146.99,128.89 146.99,127.08 146.75,126.84 145.49,126.84 144.81,127.53 144.81,130.15 144.91,130.25 145.63,130.25
N51600655 on TOP (solid shape): 26.72,110.86 26.72,110.15 26.36,109.79 24.76,109.79 24.72,109.84 24.72,110.87 24.79,110.94 26.64,110.94
N51600691 on TOP (solid shape): 26.72,112.89 26.72,112.36 26.59,112.23 24.36,112.23 24.28,112.31 24.28,112.89 24.36,112.97 24.6,112.97 24.6,112.97 25.29,112.97 25.34,113.02 26.59,113.02
N55958256 on BOTTOM (solid shape): 10.31,135.32 10.11,135.12 10.11,134.41 10.29,134.22 10.29,133.37 10.23,133.31 10.09,133.31 10.01,133.39 10.01,133.92 9.68,134.25 9.68,135.83 9.75,135.91 10.31,135.91
N55958618 on BOTTOM (solid shape): 13.59,136.27 13.59,135.63 13.46,135.5 13.18,135.5 13.06,135.37 13.06,135.01 12.45,134.41 11.73,134.41 11.48,134.15 11.48,133.37 11.43,133.31 11.3,133.31 11.28,133.34 11.28,134.53 11.61,134.86 12.14,134.86 12.62,135.35 12.62,136.26 12.67,136.31 13.56,136.31
N55958653 on BOTTOM (solid shape): 15.57,135.6 15.32,135.35 15.32,135.02 15.09,134.79 13.94,134.79 13.48,134.33 13.48,133.37 13.42,133.31 13.31,133.31 13.23,133.39 13.23,134.43 13.77,134.97 13.77,135.17 13.92,135.32 14.45,135.32 14.86,135.73 14.86,136.44 14.91,136.49 15.57,136.49
N57436918 on TOP (solid shape): 149.86,123.97 149.86,123.13 149.78,123.05 147.61,123.05 147.57,123.09 147.57,123.71 147.65,123.79 148.49,123.79 148.72,124.02 149.81,124.02
N57468968 on BOTTOM (solid shape): 70.43,101.39 70.43,99.81 70.33,99.71 68.88,99.71 68.81,99.79 68.81,100.19 68.96,100.35 69.57,100.35 69.7,100.47 69.7,100.7 69.78,100.78 69.78,101.4 69.84,101.46 70.36,101.46

Small or netless copper shapes (teardrops, artwork), in the pictures only: 80 on TOP, 60 on BOTTOM, 6 on VCC, 115 on GND1, 90 on IN1, 7 on IN2, 2 on GND2, 76 on IN3, 94 on GND3, 59 on IN4

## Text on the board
Ref Des/Silkscreen Bottom: WIRE | DOCKING | H9 | H8 | RTC | S12 | S11 | S10 | S9 | S8 | S7 | SPK | UFC | DOCKING FPC | WFC | MIC | TOUCH | USH | WLAN | DS4 | NFC | EDP | BATT | DB | WWAN
User.Comments: PARTITION_2-1120 | PARTITION_3 | PARTITION_3-O16 | PARTITION_6 | PARTITION_5-21 | PARTITION_2-930 | PARTITION_2-950 | PARTITION_2 | PARTITION_4 | PARTITION_2-21 | PARTITION_3-1120 | PARTITION_2-K21 | NotebookSchematics.com | LA-C791P | 2016-10-27 | 2015-10-27 | ROCKY | AAJA0 | ALS | IR CAMERA | UFC | DOCKING FPC | WFC | TOUCH | USH | WLAN | DS4 | NFC | BATT | WWAN | DB
Ref Des/Silkscreen Top: S1 | S2 | S3 | S4 | S5 | S6
VCC_TEXT: AMP_AGND | +0.95V_PRIM | +3.3V_VCCSPI | GND | +VCCPRIM_3P3 | +1.0V_PRIM | +VCCPRIM_CORE | +1.0V_APLL | +VCCSRAM_1P0 | +3VALW_DSW | +VCCCOREG1 | +VCCCOREG0 | +3.3V_LDO_PD | +BAT_DOCK | AGND | +5VALW | +3V_PRIM | +3VS | +1.8V_PRIM | +CHG_VIN | +0.85VS_VCCIO | B+ | +VCC_CORE | +3VALW | +VCC_GT | +5VS | +VCC_SA
User.45: Width/Space | 4.3 | 3.1 | 3.1/4.2 | 4.3/4.8 | L3/L6 | L6/L8 | L2 | L8 | L9 | 4.7 | 3.5 | 3.3 | 3 | 3.6/2.4 | 3.3/3.1 | 4.7/5.6 | 3.5/5 | 2.4 | trace Width | 2.7/2.4 | L8/L10 | IN4 | BOT | LAYER | NAME | GND1 | IN1 | IN2 | GND2 | IN3 | GND3 | TOP | VCC | 42 ohm | 80 ohm | Ref | 43 ohm | 45 ohm | 73 ohm | 70 ohm | 0_8mm_3+4+3(PTH L3-L8) (Top G-V G-V IN1 IN2 G-V IN3 G-V IN4 Bot)-150108 | STACKUP: 10 LAYER | THICKNESS=0.8mm | FIGURE | SIZE | 4.0 | DRILL CHART: VCC to IN1 | ALL UNITS ARE IN MILS | DRILL CHART: TOP to IN1 | DRILL CHART: GND1 to IN1 | DRILL CHART: VCC to GND1 | DRILL CHART: TOP to VCC | DRILL CHART: TOP to GND1 | TOLERANCE | +1.0/-1.0 | PLATED | QTY | 298 | 1530 | 69 | 49 | 386 | 2785 | DRILL CHART: GND3 to IN4 | DRILL CHART: IN3 to GND3 | DRILL CHART: IN3 to IN4 | DRILL CHART: IN4 to BOTTOM | DRILL CHART: GND3 to BOTTOM | DRILL CHART: IN3 to BOTTOM | 130 | 212 | 645 | 1316 | 2449 | 1983 | 8.0 | 16.0 | 30.0 | 31.0 | 47.0 | 59.0 | 91.0 | 110.0 | 181.0 | 35.0 | 43.0 | 63.0 | 39.0x16.0 | 47.0x24.0 | 55.0x24.0 | 63.0x24.0 | 67.0x26.0 | 71.0x59.0 | 75.0x24.0 | 75.0x26.0 | 83.0x59.0 | 37.0x30.0 | 51.0x16.0 | 55.0x16.0 | DRILL CHART: GND1 to GND3 | DRILL CHART: TOP to BOTTOM | +3.0/-3.0 | +2.0/-2.0 | NON-PLATED | 2074 | 709 | 4 | 21 | 1 | 9 | 2 | 7 | 5 | 11 | 6
